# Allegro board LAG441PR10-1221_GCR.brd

Outline 316.12 x 80.43 mm; copper layers: TOP, GND1, IN1, GND2, IN2, VCC, GND3, IN3, GND4, BOTTOM. Coordinates in mm from the lower left corner of the outline.

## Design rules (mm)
net group CHG_CSI: nets CHG_CSIN CHG_CSIP
net group CHG_CSON: nets CHG_CSON N30249106
net group CHG_CSOP: nets CHG_CSOP N30248348
net group CLK_ITPXDP_: nets CLK_ITPXDP_N CLK_ITPXDP_P
net group DDR_B_DQS5: nets DDR_B_DQS5 DDR_B_DQS#5
net group DDR_B_DQS6: nets DDR_B_DQS6 DDR_B_DQS#6
net group DDR_B_DQS7: nets DDR_B_DQS7 DDR_B_DQS#7
net group DDRA-DQS0: nets DDR_A_DQS0 DDR_A_DQS#0
net group DDRA-DQS1: nets DDR_A_DQS1 DDR_A_DQS#1
net group DDRA-DQS2: nets DDR_A_DQS2 DDR_A_DQS#2
net group DDRA-DQS3: nets DDR_A_DQS3 DDR_A_DQS#3
net group DDRA-DQS4: nets DDR_A_DQS4 DDR_A_DQS#4
net group DDRA-DQS5: nets DDR_A_DQS5 DDR_A_DQS#5
net group DDRA-DQS6: nets DDR_A_DQS6 DDR_A_DQS#6
net group DDRA-DQS7: nets DDR_A_DQS7 DDR_A_DQS#7
net group DDRB-DQS0: nets DDR_B_DQS0 DDR_B_DQS#0
net group DDRB-DQS1: nets DDR_B_DQS1 DDR_B_DQS#1
net group DDRB-DQS2: nets DDR_B_DQS2 DDR_B_DQS#2
net group DDRB-DQS3: nets DDR_B_DQS3 DDR_B_DQS#3
net group DDRB_DQS4: nets DDR_B_DQS4 DDR_B_DQS#4
net group DIFFPAIR10: nets ISH_I2C0_SCL_EDP ISH_I2C0_SDA_EDP
net group DIFFPAIR11: nets DMIC_CLK DMIC_DATA12
net group DIFFPAIR12: nets PCH_DMIC_CLK0 PCH_DMIC_DATA0
net group DIFFPAIR15: nets CPU_DP2_CTRL_CLK CPU_DP2_CTRL_DATA
net group DIFFPAIR16: nets TBT_DP1_CLK TBT_DP1_DATA
net group DIFFPAIR17: nets CPU_DP1_CTRL_CLK CPU_DP1_CTRL_DATA
net group DIFFPAIR18: nets DMIC_CLK_UA1 DMIC_DATA_UA1
net group DP2: nets VCC_SENSE VSS_SENSE
net group DP4: nets PCH_CL_CLK1 PCH_CL_DATA1
net group DP5: nets EC_TP_I2C_CLK EC_TP_I2C_DAT
net group DP6: nets TS_I2C_SCL TS_I2C_SDA
net group DP7: nets TP_I2C_DAT TP_I2C_SCL
net group DP8: nets SML1_SMBCLK SML1_SMBDATA
net group DP9: nets I2C1_SCK_TP I2C1_SDA_TP
net group DP10: nets DDR_XDP_SMBCLK DDR_XDP_SMBDAT
net group DP11: nets UPD2_SMBCLK UPD2_SMBDAT
net group DP12: nets UPD1_SMBCLK UPD1_SMBDAT
net group DP13: nets USH_EXPANDER_SMBCLK USH_EXPANDER_SMBDAT
net group DP14: nets TBT_I2C_CLK TBT_I2C_DATA
net group DP15: nets USB20_N9_L USB20_P9_L
net group DP16: nets VCCSA_SENSE VSSSA_SENSE
net group DP17: nets CLK_PCIE_N0 CLK_PCIE_P0
net group HDMI_R_CLK: nets HDMI_R_CLKN HDMI_R_CLKP
net group HDMI_R_TX_0: nets HDMI_R_TX_N0 HDMI_R_TX_P0
net group HDMI_R_TX_1: nets HDMI_R_TX_N1 HDMI_R_TX_P1
net group HDMI_R_TX_2: nets HDMI_R_TX_N2 HDMI_R_TX_P2
net group PCH_RTCX1: nets PCH_RTCX1 PCH_RTCX1_R
net group PCH_RTCX2: nets PCH_RTCX2 PCH_RTCX2_R
net group SPK_OUT_L: nets SPK_OUT_L+ SPK_OUT_L-
net group SPK_OUT_R: nets SPK_OUT_R+ SPK_OUT_R-
net group USB3_PRX_DTX_3: nets USB3_PRX_DTX_N3 USB3_PRX_DTX_P3
net group USB3_PRX_L_DTX_3: nets USB3_PRX_L_DTX_N3 USB3_PRX_L_DTX_P3
net group USB3_PRX_RD_DTX_N3: nets USB3_PRX_RD_DTX_N3 USB3_PRX_RD_DTX_P3
net group USB3_PTX_C_DRX_N3: nets USB3_PTX_C_DRX_N3 USB3_PTX_C_DRX_P3
net group USB3_PTX_C_DRX_N4: nets USB3_PTX_C_DRX_N4 USB3_PTX_DRX_N4
net group USB3_PTX_C_DRX_P4: nets USB3_PTX_C_DRX_P4 USB3_PTX_DRX_P4
net group USB3_PTX_RD_DRX_N3: nets USB3_PTX_RD_DRX_N3 USB3_PTX_RD_DRX_P3
net group VCCGT_SENSE: nets VCCGT_SENSE VCCGT_SENSE_R
net group VSSGT_SENSE: nets VSSGT_SENSE VSSGT_SENSE_R
net group XTAL24_IN: nets XTAL24_IN XTAL24_IN_R
net group XTAL24_OUT: nets XTAL24_OUT XTAL24_OUT_R
net group AR: nets TBT_A_AUX_N TBT_A_AUX_N_C TBT_A_AUX_P TBT_A_AUX_P_C TBT_A_TRX_DTX_N1 TBT_A_TRX_DTX_N2 TBT_A_TRX_DTX_P1 TBT_A_TRX_DTX_P2 TBT_A_TTX_C_DRX_N1 TBT_A_TTX_C_DRX_N2 TBT_A_TTX_C_DRX_P1 TBT_A_TTX_C_DRX_P2 TBT_A_TTX_DRX_N1 TBT_A_TTX_DRX_N2 TBT_A_TTX_DRX_P1 TBT_A_TTX_DRX_P2 TBT_B_AUX_N TBT_B_AUX_N_C TBT_B_AUX_P TBT_B_AUX_P_C TBT_B_TRX_DTX_N1 TBT_B_TRX_DTX_N2 TBT_B_TRX_DTX_P1 TBT_B_TRX_DTX_P2 TBT_B_TTX_C_DRX_N1 TBT_B_TTX_C_DRX_N2 TBT_B_TTX_C_DRX_P1 TBT_B_TTX_C_DRX_P2 TBT_B_TTX_DRX_N1 TBT_B_TTX_DRX_N2 TBT_B_TTX_DRX_P1 TBT_B_TTX_DRX_P2
net group AR-CONN: nets TBT_A_I2C_B_N TBT_A_I2C_B_N_R TBT_A_I2C_B_P TBT_A_I2C_B_P_R TBT_A_USB2_T_N TBT_A_USB2_T_N_R TBT_A_USB2_T_P TBT_A_USB2_T_P_R TBT_B_I2C_B_N TBT_B_I2C_B_N_R TBT_B_I2C_B_P TBT_B_I2C_B_P_R TBT_B_USB2_T_N TBT_B_USB2_T_N_R TBT_B_USB2_T_P TBT_B_USB2_T_P_R
net group CNVI: nets CLK_CNV_PRX_DTX_N CLK_CNV_PRX_DTX_P CLK_CNV_PTX_DRX_N CLK_CNV_PTX_DRX_P CNV_PRX_DTX_N0 CNV_PRX_DTX_N1 CNV_PRX_DTX_P0 CNV_PRX_DTX_P1 CNV_PTX_DRX_N0 CNV_PTX_DRX_N1 CNV_PTX_DRX_P0 CNV_PTX_DRX_P1
net group CNVI_S: nets CNV_BRI_PRX_DTX CNV_BRI_PRX_R_DTX CNV_BRI_PTX_R_DRX CNV_RGI_PRX_DTX CNV_RGI_PRX_R_DTX CNV_RGI_PTX_DRX CNV_RGI_PTX_R_DRX
net group CRYSTAL: nets MEC_XTAL1 MEC_XTAL2 MEC_XTAL2_R XTAL_25_IN XTAL_25_IN_R XTAL_25_OUT XTAL_25_OUT_R
net group DDI1: nets CPU_DP1_AUXN CPU_DP1_AUXN_C CPU_DP1_AUXP CPU_DP1_AUXP_C CPU_DP1_N0 CPU_DP1_N0_C CPU_DP1_N1 CPU_DP1_N1_C CPU_DP1_N2 CPU_DP1_N2_C CPU_DP1_N3 CPU_DP1_N3_C CPU_DP1_P0 CPU_DP1_P0_C CPU_DP1_P1 CPU_DP1_P1_C CPU_DP1_P2 CPU_DP1_P2_C CPU_DP1_P3 CPU_DP1_P3_C
net group DDI2: nets CPU_DP2_AUXN CPU_DP2_AUXN_C CPU_DP2_AUXP CPU_DP2_AUXP_C CPU_DP2_N0 CPU_DP2_N0_C CPU_DP2_N1 CPU_DP2_N1_C CPU_DP2_N2 CPU_DP2_N2_C CPU_DP2_N3 CPU_DP2_N3_C CPU_DP2_P0 CPU_DP2_P0_C CPU_DP2_P1 CPU_DP2_P1_C CPU_DP2_P2 CPU_DP2_P2_C CPU_DP2_P3 CPU_DP2_P3_C
net group DDR-OTHER: nets DDR_A0_ZQ0 DDR_A0_ZQ1 DDR_A1_ZQ0 DDR_A1_ZQ1 DDR_B0_ZQ0 DDR_B0_ZQ1 DDR_B1_ZQ0 DDR_B1_ZQ1
net group DDR_A_CA1: nets DDR_A_CA1_0 DDR_A_CA1_1 DDR_A_CA1_2 DDR_A_CA1_3 DDR_A_CA1_4 DDR_A_CA1_5 DDR_A_CA1_6 DDR_A_CA1_7 DDR_A_CA1_8 DDR_A_CA1_9
net group DDR_A_CA2: nets DDR_A_CA2_0 DDR_A_CA2_1 DDR_A_CA2_2 DDR_A_CA2_3 DDR_A_CA2_4 DDR_A_CA2_5 DDR_A_CA2_6 DDR_A_CA2_7 DDR_A_CA2_8 DDR_A_CA2_9
net group DDR_A_CKE: nets DDR_A_CKE0 DDR_A_CKE1 DDR_A_CKE2 DDR_A_CKE3
net group DDR_B_CA1: nets DDR_B_CA1_0 DDR_B_CA1_1 DDR_B_CA1_2 DDR_B_CA1_3 DDR_B_CA1_4 DDR_B_CA1_5 DDR_B_CA1_6 DDR_B_CA1_7 DDR_B_CA1_8 DDR_B_CA1_9
net group DDR_B_CA2: nets DDR_B_CA2_0 DDR_B_CA2_1 DDR_B_CA2_2 DDR_B_CA2_3 DDR_B_CA2_4 DDR_B_CA2_5 DDR_B_CA2_6 DDR_B_CA2_7 DDR_B_CA2_8 DDR_B_CA2_9
net group DDR_B_CKE: nets DDR_B_CKE0 DDR_B_CKE1 DDR_B_CKE2 DDR_B_CKE3
net group DDRA-D0: nets DDR_A_D0 DDR_A_D1 DDR_A_D2 DDR_A_D3 DDR_A_D4 DDR_A_D5 DDR_A_D6 DDR_A_D7
net group DDRA-D1: nets DDR_A_D8 DDR_A_D9 DDR_A_D10 DDR_A_D11 DDR_A_D12 DDR_A_D13 DDR_A_D14 DDR_A_D15
net group DDRA-D2: nets DDR_A_D16 DDR_A_D17 DDR_A_D18 DDR_A_D19 DDR_A_D20 DDR_A_D21 DDR_A_D22 DDR_A_D23
net group DDRA-D3: nets DDR_A_D24 DDR_A_D25 DDR_A_D26 DDR_A_D27 DDR_A_D28 DDR_A_D29 DDR_A_D30 DDR_A_D31
net group DDRA-D4: nets DDR_A_D32 DDR_A_D33 DDR_A_D34 DDR_A_D35 DDR_A_D36 DDR_A_D37 DDR_A_D38 DDR_A_D39
net group DDRA-D5: nets DDR_A_D40 DDR_A_D41 DDR_A_D42 DDR_A_D43 DDR_A_D44 DDR_A_D45 DDR_A_D46 DDR_A_D47
net group DDRA-D6: nets DDR_A_D48 DDR_A_D49 DDR_A_D50 DDR_A_D51 DDR_A_D52 DDR_A_D53 DDR_A_D54 DDR_A_D55
net group DDRA-D7: nets DDR_A_D56 DDR_A_D57 DDR_A_D58 DDR_A_D59 DDR_A_D60 DDR_A_D61 DDR_A_D62 DDR_A_D63
net group DDRB-D0: nets DDR_B_D0 DDR_B_D1 DDR_B_D2 DDR_B_D3 DDR_B_D4 DDR_B_D5 DDR_B_D6 DDR_B_D7
net group DDRB-D1: nets DDR_B_D8 DDR_B_D9 DDR_B_D10 DDR_B_D11 DDR_B_D12 DDR_B_D13 DDR_B_D14 DDR_B_D15
net group DDRB-D2: nets DDR_B_D16 DDR_B_D17 DDR_B_D18 DDR_B_D19 DDR_B_D20 DDR_B_D21 DDR_B_D22 DDR_B_D23
net group DDRB-D3: nets DDR_B_D24 DDR_B_D25 DDR_B_D26 DDR_B_D27 DDR_B_D28 DDR_B_D29 DDR_B_D30 DDR_B_D31
net group DDRB-D4: nets DDR_B_D32 DDR_B_D33 DDR_B_D34 DDR_B_D35 DDR_B_D36 DDR_B_D37 DDR_B_D38 DDR_B_D39
net group DDRB-D5: nets DDR_B_D40 DDR_B_D41 DDR_B_D42 DDR_B_D43 DDR_B_D44 DDR_B_D45 DDR_B_D46 DDR_B_D47
net group DDRB-D6: nets DDR_B_D48 DDR_B_D49 DDR_B_D50 DDR_B_D51 DDR_B_D52 DDR_B_D53 DDR_B_D54 DDR_B_D55
net group DDRB-D7: nets DDR_B_D56 DDR_B_D57 DDR_B_D58 DDR_B_D59 DDR_B_D60 DDR_B_D61 DDR_B_D62 DDR_B_D63
net group EDP: nets EDP_AUXN EDP_AUXN_R EDP_AUXP EDP_AUXP_R EDP_TXN0 EDP_TXN0_R EDP_TXN1 EDP_TXN1_R EDP_TXP0 EDP_TXP0_R EDP_TXP1 EDP_TXP1_R
net group HDMI: nets TBT_DP0_N0 TBT_DP0_P0 TBT_DP1_N1 TBT_DP1_P1 TBT_DP2_N2 TBT_DP2_P2 TBT_DP3_N3 TBT_DP3_P3
net group HDMI-100H: nets HDMI_CLKN HDMI_CLKP HDMI_TX_N0 HDMI_TX_N1 HDMI_TX_N2 HDMI_TX_P0 HDMI_TX_P1 HDMI_TX_P2
net group PCIE: nets PCIE_PRX_C_DTX_N1 PCIE_PRX_C_DTX_N9 PCIE_PRX_C_DTX_N10 PCIE_PRX_C_DTX_N11 PCIE_PRX_C_DTX_N12 PCIE_PRX_C_DTX_N13 PCIE_PRX_C_DTX_N14 PCIE_PRX_C_DTX_N15 PCIE_PRX_C_DTX_N16 PCIE_PRX_C_DTX_P1 PCIE_PRX_C_DTX_P9 PCIE_PRX_C_DTX_P10 PCIE_PRX_C_DTX_P11 PCIE_PRX_C_DTX_P12 PCIE_PRX_C_DTX_P13 PCIE_PRX_C_DTX_P14 PCIE_PRX_C_DTX_P15 PCIE_PRX_C_DTX_P16 PCIE_PRX_DTX_N1 PCIE_PRX_DTX_N6 PCIE_PRX_DTX_N7 PCIE_PRX_DTX_N8 PCIE_PRX_DTX_N9 PCIE_PRX_DTX_N10 PCIE_PRX_DTX_N11 PCIE_PRX_DTX_N12 PCIE_PRX_DTX_N13 PCIE_PRX_DTX_N14 PCIE_PRX_DTX_N15 PCIE_PRX_DTX_N16 PCIE_PRX_DTX_P1 PCIE_PRX_DTX_P6 PCIE_PRX_DTX_P7 PCIE_PRX_DTX_P8 PCIE_PRX_DTX_P9 PCIE_PRX_DTX_P10 PCIE_PRX_DTX_P11 PCIE_PRX_DTX_P12 PCIE_PRX_DTX_P13 PCIE_PRX_DTX_P14 PCIE_PRX_DTX_P15 PCIE_PRX_DTX_P16 PCIE_PTX_C_DRX_N1 PCIE_PTX_C_DRX_N6 PCIE_PTX_C_DRX_N7 PCIE_PTX_C_DRX_N9 PCIE_PTX_C_DRX_N10 PCIE_PTX_C_DRX_N11 PCIE_PTX_C_DRX_N12 PCIE_PTX_C_DRX_N13 PCIE_PTX_C_DRX_N14 PCIE_PTX_C_DRX_N15 PCIE_PTX_C_DRX_N16 PCIE_PTX_C_DRX_P1 PCIE_PTX_C_DRX_P6 PCIE_PTX_C_DRX_P7 PCIE_PTX_C_DRX_P8 PCIE_PTX_C_DRX_P9 PCIE_PTX_C_DRX_P10 PCIE_PTX_C_DRX_P11 PCIE_PTX_C_DRX_P12 PCIE_PTX_C_DRX_P13 PCIE_PTX_C_DRX_P14 PCIE_PTX_C_DRX_P15 PCIE_PTX_C_DRX_P16 PCIE_PTX_DRX_N6 PCIE_PTX_DRX_N7 PCIE_PTX_DRX_N9 PCIE_PTX_DRX_N10 PCIE_PTX_DRX_N11 PCIE_PTX_DRX_N12 PCIE_PTX_DRX_N13 PCIE_PTX_DRX_N14 PCIE_PTX_DRX_N15 PCIE_PTX_DRX_N16 PCIE_PTX_DRX_P6 PCIE_PTX_DRX_P7 PCIE_PTX_DRX_P9 PCIE_PTX_DRX_P10 PCIE_PTX_DRX_P11 PCIE_PTX_DRX_P12 PCIE_PTX_DRX_P13 PCIE_PTX_DRX_P14 PCIE_PTX_DRX_P15 PCIE_PTX_DRX_P16 USB3_MRX_DTX_N4 USB3_MRX_DTX_P4 USB3_MTX_DRX_N4 USB3_MTX_DRX_P4 USB3_PRX_DTX_N4 USB3_PRX_DTX_P4
net group PCIE_15: nets PCIE_PTX_DRX_N1 PCIE_PTX_DRX_N8 PCIE_PTX_DRX_P1 PCIE_PTX_DRX_P8
net group PLATFORM-CLK: nets CLK_PCIE_N1 CLK_PCIE_N1_R CLK_PCIE_N2 CLK_PCIE_N2_R CLK_PCIE_N4 CLK_PCIE_N4_R CLK_PCIE_N5 CLK_PCIE_N5_R CLK_PCIE_P1 CLK_PCIE_P1_R CLK_PCIE_P2 CLK_PCIE_P2_R CLK_PCIE_P4 CLK_PCIE_P4_R CLK_PCIE_P5 CLK_PCIE_P5_R CLKREQ_PCIE#0 CLKREQ_PCIE#1 CLKREQ_PCIE#2 CLKREQ_PCIE#3 CLKREQ_PCIE#4 CLKREQ_PCIE#5 PCIE_PRX_R_DTX_N8 PCIE_PRX_R_DTX_P8 PCIE_PTX_C_DRX_N8 PCIE_PTX_R_DRX_N8 PCIE_PTX_R_DRX_P8
net group S-5: nets BC_DAT_ECE1117 CHG_DAT CPU_XDP_TDI CPU_XDP_TDO CPU_XDP_TMS DAT_SMB IMVP_SMBDAT IMVP_VR_SMBDAT ISH_I2C0_SDA ISH_I2C0_SDA_R ISH_I2C1_SDA JTAG_TDI JTAG_TDO JTAG_TMS MEM_SMBDATA MSDATA PBAT_CHARGER_SMBDAT PCH_JTAG_TDI PCH_JTAG_TDO PCH_JTAG_TMS PCH_JTAGX PCH_SPI_CS0# PCH_SPI_CS0#_R PCH_SPI_CS1# PCH_SPI_CS1#_R PCH_SPI_CS2# PCH_SPI_CS2#_TPM PCH_SPI_IO2 PCH_SPI_IO2_R PCH_SPI_IO3 PCH_SPI_IO3_R PCH_SPI_SI PCH_SPI_SI_R PCH_SPI_SI_TPM PCH_SPI_SO PCH_SPI_SO_R PCH_SPI_SO_TPM PS_SMBDAT SD_CMD SD_CMD_R SD_D0 SD_D0_R SD_D1 SD_D1_R SD_D2 SD_D2_R SD_D3 SD_D3_R SML0_SMBDATA SP7_SDWP SPI_CLK_VROM0 SPI_IO2_VROM0 SPI_IO3_VROM0 SPI_SI_VROM0 SPI_SO_VROM0 SYS_PWROK TPM_PIRQ# TS_I2C_SDA_R UIM_DATA UPD1_SMBINT# UPD2_SMBINT# XDP_ITP_PMODE XDP_TCK0 XDP_TDI XDP_TDO XDP_TMS
net group S-9: nets BEEP CBN CBP CFG_RCOMP CHG_COMP CLK_TP_SIO_I2C_DAT CLKREQ_CNV CNV_RF_RESET CNV_RF_RESET# CNV_RF_RESET#_R CNVI_EN# CPU_POPIRCOMP CPU_XDP_TRST# CPVEE DMIC_CLK0 DMIC_DATA0 DPSNK1_DDC_CLK EDP_RCOMP EDRAM_OPIO_RCOMP EMMC_RCOMP EOPIO_RCOMP ESPI_ALERT# ESPI_CS# ESPI_IO0 ESPI_IO0_R ESPI_IO1 ESPI_IO1_R ESPI_IO2 ESPI_IO2_R ESPI_IO3 ESPI_IO3_R ESPI_RESET# FPR_RESET# H_CATERR# H_CPU_SVIDALRT# H_CPUPWRGD H_PROCHOT# H_PROCHOT#_R H_THERMTRIP# HDA_RST# HDA_RST#_R HDA_SDIN0 HDA_SDIN0_R HDA_SDOUT HDA_SDOUT_R HDA_SYNC HDA_SYNC_R HPOL_CONN HPOR_CONN HPOUT-L HPOUT-L_L HPOUT-R HPOUT-R_L HRESET_PD1 HRESET_PD2 JTAG_RST# LINE2-L LINE2-R MIC2-VREFO-L MIC2-VREFO-R MONO_IN PCH_CL_RST1# PCH_JTAG_TRST# PCH_PLTRST# PCH_PLTRST#_5105 PCH_PLTRST#_AND PCH_POPIRCOMP PCH_RSMRST# PCH_RSMRST#_AND PCH_RTCRST# PCH_TBT_PERST# PCIE_RCOMPN PCIE_RCOMPP PECI_EC PECI_EC_R REM_DIODE1_N REM_DIODE1_P REM_DIODE2_N REM_DIODE2_P REM_DIODE3_N REM_DIODE3_P RESET_IN# RESET_OUT RING2 RTCRST_ON RTCRST_ON_POWER RTCRST_ON_R SD_RCOMP SM_RCOMP0 SM_RCOMP1 SM_RCOMP2 SPKR SRTCRST# SYS_RESET# TBT_A_MRESET TBT_A_RESET_N TBT_B_RESET_N TBT_RESET_N_EC TBT_RESET_N_R TS_RST# TS_RST#_R UIM_RESET VCCST_PWRGD VCCST_PWRGD_CPU VIDSCLK_R VIDSOUT_R VR_SVID_ALERT# VR_SVID_CLK VR_SVID_DATA WWAN_BB_RST# WWAN_BB_RST#_R WWAN_GPIO_PERST# WWAN_GPIO_PERST#_R WWAN_PERST# WWAN_PERST#_R XDP_BPM#0 XDP_BPM#1 XDP_BPM#2_R XDP_BPM#3_R XDP_TRST#
net group S-12: nets BC_CLK_ECE1117 CHG_CLK CLK_SMB DAT_TP_SIO_I2C_CLK ESPI_CLK ESPI_CLK_5105 HDA_BIT_CLK HDA_BIT_CLK_R IMVP_SMBCLK IMVP_VR_SMBCLK ISH_I2C0_SCL ISH_I2C0_SCL_R ISH_I2C1_SCL MEM_SMBCLK MSCLK PBAT_CHARGER_SMBCLK PCH_SPI_CLK PCH_SPI_CLK_R PCH_SPI_CLK_TPM PS_SMBCLK SD_CLK SD_CLK_R SML0_SMBCLK TBT_A_CC1 TBT_A_CC2 TBT_B_CC1 TBT_B_CC2 TS_I2C_SCL_R UIM_CLK
net group SD-100H: nets SD_LN0_M SD_LN0_P SD_LN1_M SD_LN1_P
net group USB3_PTX_DRX_3: nets USB3_PTX_DRX_P3
net group USB3_PTX_L_DRX_3: nets USB3_PTX_L_DRX_N3
net group USB20: nets CHR_USB20_N3 CHR_USB20_N3_R CHR_USB20_N4 CHR_USB20_N4_R CHR_USB20_P3 CHR_USB20_P3_R CHR_USB20_P4 CHR_USB20_P4_R FP_USB+ FP_USB- USB20_N1 USB20_N2 USB20_N3 USB20_N4 USB20_N6 USB20_N6_R USB20_N7 USB20_N7_R USB20_N8 USB20_N8_R USB20_N9 USB20_N9_R USB20_N10 USB20_N10_R USB20_P1 USB20_P2 USB20_P3 USB20_P4 USB20_P6 USB20_P6_R USB20_P7 USB20_P7_R USB20_P8 USB20_P8_R USB20_P9 USB20_P9_R USB20_P10 USB20_P10_R
net group USB30: nets USB3_MRX_L_DTX_N4 USB3_MRX_L_DTX_P4 USB3_MTX_L_DRX_N4 USB3_MTX_L_DRX_P4 USB3_PRX_C_RD_DTX_N3 USB3_PRX_C_RD_DTX_P3 USB3_PRX_DTX_N2 USB3_PRX_DTX_P2 USB3_PRX_L_DTX_N2 USB3_PRX_L_DTX_P2 USB3_PTX_C_DRX_N2 USB3_PTX_C_DRX_P2 USB3_PTX_C_RD_DRX_N3 USB3_PTX_C_RD_DRX_P3 USB3_PTX_DRX_N2 USB3_PTX_DRX_N3 USB3_PTX_DRX_P2 USB3_PTX_L_DRX_N2 USB3_PTX_L_DRX_P2 USB3_PTX_L_DRX_P3
net group W10: nets TBT_RSENSE VBUSSENSE VCC_SENSE_R VSS_SENSE_R
net group XDP_4/3/3/3/4: nets CPU_XDP_TCK JTAG_CLK PCH_JTAG_TCK XDP_TCK1
nets with their own width: min track width 0.254; nets BAT1_LED#_R BAT2_LED#_R CAPS_LED F4_LED
nets with their own width: min track width 0.381; nets +3V_PCH_DSW_R
nets with their own width: min track width 0.508; nets +1.0V_VCCSTG_R +3V_FPR +3V_PCH AGND CHG_ADP GND KB_LED_PWM# VDD
nets with their own width: min track width 0.762; nets CHG_DCIN
nets with their own width: min track width 1.016; nets B+ RING2_CONN SLEEVE SLEEVE_CONN

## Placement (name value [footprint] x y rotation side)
C14  0.1U_0201_10V6K  [C_0201]  133.36 16.39 270 bottom
C15  100P_0201_50V8J  [C_0201]  303.32 64.8 0 bottom
C18  0.1U_0201_10V6K  [C_0201]  303.32 64.22 0 bottom
C21  0.1U_0201_10V6K  [C_0201]  200.89 32.11 90 bottom
C22  10U_0402_10V6M  [C_0402]  201.7 32.02 0 bottom
C26  0.1U_0201_10V6K  [C_0201]  188.89 19.28 90 bottom
C27  470P_0201_25V7K  [C_0201]  185.33 17.51 90 bottom
C28  1U_0201_6.3V6M  [C_0201]  254.1 42.08 90 top
C29  0.1U_0201_10V6K  [C_0201]  257.28 36.11 90 top
C30  470P_0201_25V7K  [C_0201]  48.09 74.81 90 top
C31  0.1U_0201_10V6K  [C_0201]  185.77 12.76 270 bottom
C32  0.1U_0201_10V6K  [C_0201]  47.24 69.45 90 top
C37  470P_0201_25V7K  [C_0201]  255.5 36.7 270 top
C38  470P_0201_25V7K  [C_0201]  254.86 36.7 270 top
C39  1U_0201_6.3V6M  [C_0201]  256.13 42.08 90 top
C41  0.1U_0201_10V6K  [C_0201]  253 36.11 90 top
C48  0.1U_0201_10V6K  [C_0201]  201.84 32.44 270 top
C49  1U_0201_6.3V6M  [C_0201]  195.59 33.07 180 top
C50  470P_0201_25V7K  [C_0201]  200.14 32.52 0 top
C51  470P_0201_25V7K  [C_0201]  200.14 31.57 0 top
C52  0.1U_0201_10V6K  [C_0201]  202.41 30.5 0 top
C53  1U_0201_6.3V6M  [C_0201]  195.59 31.92 180 top
C56  0.1U_0201_10V6K  [C_0201]  221.84 62.1 270 top
C57  0.1U_0201_10V6K  [C_0201]  224 56.64 270 top
C59  1000P_0201_50V7K  [C_0201]  224.89 61.51 90 top
C60  470P_0201_25V7K  [C_0201]  222.48 50.78 90 top
C61  0.1U_0201_10V6K  [C_0201]  227.05 50.27 90 top
C62  0.1U_0201_10V6K  [C_0201]  221.93 47.64 0 top
C70  0.1U_0201_10V6K  [C_0201]  120.5 29.1 0 top
C71  470P_0201_25V7K  [C_0201]  123.61 31.51 0 top
C72  1U_0201_6.3V6M  [C_0201]  121.7 28.28 90 top
C73  470P_0201_25V7K  [C_0201]  124.81 31.51 0 top
C74  0.1U_0201_10V6K  [C_0201]  128.31 30.41 90 top
C75  1U_0201_6.3V6M  [C_0201]  126.02 28.66 90 top
C78  0.1U_0201_10V6K  [C_0201]  48 76.38 0 top
C85  1U_0201_6.3V6M  [C_0201]  228.15 42.94 0 top
C86  1U_0201_6.3V6M  [C_0201]  227.68 50.27 90 top
C88  0.47U_0201_6.3V6K  [C_0201]  99.17 21.7 180 top
C92  2.2U_0201_6.3V6M  [C_0201]  148.67 20.22 270 bottom
C93  0.1U_0201_10V6K  [C_0201]  300.93 58.98 90 bottom
C94  0.1U_0201_10V6K  [C_0201]  33.63 51.96 270 top
C95  0.1U_0201_10V6K  [C_0201]  30.9 51.96 270 top
C96  0.33U_0201_6.3V6M  [C_0201]  136.17 17.49 90 bottom
C97  0.33U_0201_6.3V6M  [C_0201]  135.61 17.49 90 bottom
CA1  0.1U_0201_10V6K  [C_0201]  292.45 25.1 180 top
CA4  0.22U_0201_10V6K  [C_0201]  292.42 26.31 0 top
CA5  10U_0402_10V6M  [C_0402]  288.77 28.83 90 top
CA6  100P_0201_50V8J  [C_0201]  292.45 25.74 0 top
CA7  10U_0402_6.3V6M  [C_0402]  289.53 23.77 0 top
CA8  330P_0201_50V7K  [C_0201]  288.9 19.7 270 top
CA9  330P_0201_50V7K  [C_0201]  288.9 20.34 0 top
CA10  2.2U_0603_6.3V6K  [C_0603]  290.68 19.2 0 top
CA11  10U_0402_6.3V6M  [C_0402]  278.04 25.37 270 top
CA12  0.1U_0201_10V6K  [C_0201]  278.8 25.52 270 top
CA13  2.2U_0201_6.3V6M  [C_0201]  288.64 27.36 270 top
CA14  0.1U_0201_10V6K  [C_0201]  287.06 29 90 top
CA15  10U_0402_6.3V6M  [C_0402]  290.5 27.77 180 top
CA16  10U_0402_6.3V6M  [C_0402]  287.82 28.83 90 top
CA18  10U_0402_6.3V6M  [C_0402]  286.16 19.04 270 top
CA19  10U_0402_6.3V6M  [C_0402]  283.16 18.5 270 top
CA20  10U_0402_6.3V6M  [C_0402]  285.23 33.66 180 bottom
CA21  0.1U_0201_10V6K  [C_0201]  284.61 32.56 225 bottom
CA22  10U_0402_6.3V6M  [C_0402]  285.34 30.18 45 bottom
CA23  0.1U_0201_10V6K  [C_0201]  284.43 31.06 135 bottom
CA24  0.1U_0201_10V6K  [C_0201]  284.71 19.2 0 top
CA25  10U_0402_6.3V6M  [C_0402]  284.38 18.43 0 top
CA26  10U_0402_6.3V6M  [C_0402]  281.66 18.45 270 top
CA27  0.1U_0201_10V6K  [C_0201]  282.42 18.6 270 top
CA28  22P_0201_25V8  [C_0201]  280.75 19.7 180 top
CA29  10U_0402_6.3V6M  [C_0402]  280.39 29.09 90 top
CA30  0.1U_0201_10V6K  [C_0201]  281.15 29 90 top
CA31  0.1U_0201_10V6K  [C_0201]  278.21 26.12 180 top
CA32  1U_0201_6.3V6M  [C_0201]  277.62 26.75 0 top
CA34  33P_0201_50V8J  [C_0201]  276.72 23.58 180 top
CA35  10P_0201_50V8J  [C_0201]  276.72 22.94 180 top
CA36  0.1U_0201_10V6K  [C_0201]  279.59 29.03 90 top
CA42  10U_0603_6.3V6M  [C_0603]  289.66 26.05 0 top
CA43  10U_0603_6.3V6M  [C_0603]  289.66 24.85 0 top
CA44  100P_0201_50V8J  [C_0201]  292.42 20.34 0 top
CA45  100P_0201_50V8J  [C_0201]  292.45 24.53 180 top
CA46  680P_0201_50V7K  [C_0201]  299.06 15.64 180 top
CA47  680P_0201_50V7K  [C_0201]  294.93 25.8 90 top
CA48  100P_0201_50V8J  [C_0201]  291.95 21.61 270 top
CA49  100P_0201_50V8J  [C_0201]  291.95 22.88 270 top
CA84  1000P_0201_50V7K  [C_0201]  295.21 13.88 180 top
CA85  1000P_0201_50V7K  [C_0201]  296.65 13.88 0 top
CA86  1000P_0201_50V7K  [C_0201]  293.1 13.88 0 top
CA87  1000P_0201_50V7K  [C_0201]  291.65 13.88 180 top
CA141  0.1U_0201_10V6K  [C_0201]  281.14 12.07 90 top
CA144  470P_0201_25V7K  [C_0201]  266.55 36.7 270 top
CA145  1000P_0201_50V7K  [C_0201]  265.98 36.7 270 top
CA146  1U_0201_6.3V6M  [C_0201]  265.21 42.08 90 top
CA147  0.1U_0201_10V6K  [C_0201]  266.04 35.45 270 top
CA148  0.1U_0201_10V6K  [C_0201]  268.32 36.11 90 top
CA149  1U_0201_6.3V6M  [C_0201]  267.25 42.08 90 top
CA150  680P_0201_50V7K  [C_0201]  305.79 24.78 90 top
CA151  680P_0201_50V7K  [C_0201]  303.63 24.78 90 top
CA152  2.2U_0603_6.3V6K  [C_0603]  287.41 18.01 90 top
CA153  0.1U_0201_10V6K  [C_0201]  281.52 16.49 270 top
CA154  2P_0201_25V8B  [C_0201]  279.54 19.13 180 top
CA155  470P_0201_25V7K  [C_0201]  283.44 15.08 0 top
CB15  1U_0201_6.3V6M  [C_0201]  310.23 5.1 180 top
CB16  1U_0201_6.3V6M  [C_0201]  308.42 4.34 0 top
CB17  22P_0201_25V8  [C_0201]  310.62 1.69 90 top
CB18  0.1U_0201_10V6K  [C_0201]  312.3 4.59 0 top
CB19  0.1U_0201_10V6K  [C_0201]  268.52 14.92 270 top
CB20  0.1U_0201_10V6K  [C_0201]  269.79 14.92 270 top
CB21  0.1U_0201_10V6K  [C_0201]  267.25 14.92 270 top
CB22  0.1U_0201_10V6K  [C_0201]  271.06 14.92 270 top
CC2  12P_0201_50V8J  [C_0201]  102.31 30.54 0 top
CC4  0.1U_0201_10V6K  [C_0201]  104.11 12.05 90 top
CC6  15P_0201_50V8J  [C_0201]  108.91 59.61 0 bottom
CC7  15P_0201_50V8J  [C_0201]  107.16 59.61 180 bottom
CC8  10P_0201_50V8J  [C_0201]  98.78 25.93 0 bottom
CC9  1U_0201_6.3V6M  [C_0201]  98.91 30.63 270 bottom
CC10  10P_0201_50V8J  [C_0201]  98.14 25.93 180 bottom
CC11  1U_0201_6.3V6M  [C_0201]  96.91 28.09 180 bottom
CC12  0.01U_0201_10V6K  [C_0201]  99.8 27.83 270 bottom
CC13  22P_0201_25V8  [C_0201]  96.87 30.63 270 bottom
CC15  2P_0201_25V8B  [C_0201]  96.24 29.36 270 bottom
CC17  2P_0201_25V8B  [C_0201]  94.97 29.36 180 bottom
CC31  10U_0402_6.3V6M  [C_0402]  94.25 29.28 0 top
CC32  22U_0603_6.3V6M  [C_0603]  83.48 30.37 180 bottom
CC33  10U_0402_6.3V6M  [C_0402]  90.99 30.64 270 bottom
CC34  10U_0402_6.3V6M  [C_0402]  84.48 30.6 0 bottom
CC35  10U_0402_6.3V6M  [C_0402]  81.08 30.5 180 bottom
CC36  10U_0402_6.3V6M  [C_0402]  86.26 30.6 0 bottom
CC37  10U_0402_6.3V6M  [C_0402]  88.95 30.6 180 bottom
CC38  10U_0402_6.3V6M  [C_0402]  89.95 30.64 270 bottom
CC39  10U_0402_6.3V6M  [C_0402]  95.39 45.81 90 top
CC40  10U_0402_6.3V6M  [C_0402]  82.36 41.52 180 top
CC41  10U_0402_6.3V6M  [C_0402]  95.97 42.18 0 top
CC42  10U_0402_6.3V6M  [C_0402]  83.25 41.5 0 top
CC45  10U_0402_6.3V6M  [C_0402]  96.9 26.21 90 top
CC46  10U_0402_6.3V6M  [C_0402]  73.82 25.98 90 top
CC47  1U_0201_6.3V6M  [C_0201]  71.56 29.36 0 top
CC48  1U_0201_6.3V6M  [C_0201]  96.11 26.21 90 top
CC49  1U_0201_6.3V6M  [C_0201]  81.76 27.04 270 top
CC50  1U_0201_6.3V6M  [C_0201]  74.59 25.82 90 top
CC51  10U_0402_6.3V6M  [C_0402]  95.97 43.07 0 top
CC52  10U_0402_6.3V6M  [C_0402]  96.3 45.81 90 top
CC53  1U_0201_6.3V6M  [C_0201]  97.13 45.64 0 top
CC54  1U_0201_6.3V6M  [C_0201]  92.99 40.99 180 top
CC55  1U_0201_6.3V6M  [C_0201]  83.25 39.83 0 top
CC56  1U_0201_6.3V6M  [C_0201]  82.37 39.83 180 top
CC65  1U_0201_6.3V6M  [C_0201]  99.1 41.17 90 top
CC66  1U_0201_6.3V6M  [C_0201]  100.43 44.98 0 top
CC67  1U_0201_6.3V6M  [C_0201]  97.7 43.66 90 top
CC68  1U_0201_6.3V6M  [C_0201]  97.13 43.83 90 top
CC69  1U_0201_6.3V6M  [C_0201]  109.31 43.02 90 top
CC70  22U_0603_6.3V6M  [C_0603]  100.07 47.67 180 top
CC72  0.1U_0201_10V6K  [C_0201]  98.27 42.4 90 top
CC73  1U_0201_6.3V6M  [C_0201]  97.7 42.4 90 top
CC76  1U_0201_6.3V6M  [C_0201]  97.7 41.13 90 top
CC80  1U_0201_6.3V6M  [C_0201]  99.72 57.48 0 bottom
CC83  1U_0201_6.3V6M  [C_0201]  113.16 53.43 0 bottom
CC85  0.1U_0201_10V6K  [C_0201]  56.72 67.84 180 top
CC86  0.1U_0201_10V6K  [C_0201]  56.72 67.27 180 top
CC87  0.1U_0201_10V6K  [C_0201]  54.43 67.76 0 top
CC88  0.1U_0201_10V6K  [C_0201]  60.83 67.58 0 top
CC89  0.1U_0201_10V6K  [C_0201]  58.48 67.84 0 top
CC92  0.1U_0201_6.3V6K  [C_0201]  56.35 30.96 270 bottom
CC98  1U_0201_6.3V6M  [C_0201]  111.68 45.27 0 bottom
CC100  22U_0603_6.3V6M  [C_0603]  113 54.32 0 bottom
CC101  1U_0201_6.3V6M  [C_0201]  98.27 41.13 90 top
CC102  22U_0603_6.3V6M  [C_0603]  99.67 58.64 180 bottom
CC199  100P_0201_50V8J  [C_0201]  85.57 57.83 90 bottom
CC200  100P_0201_50V8J  [C_0201]  93.59 59.03 180 bottom
CC201  1U_0201_6.3V6M  [C_0201]  92.43 59.05 90 bottom
CC202  1U_0201_6.3V6M  [C_0201]  97.14 57.37 90 bottom
CC203  1U_0201_6.3V6M  [C_0201]  95.39 40.4 180 top
CC232  10U_0402_6.3V6M  [C_0402]  96.04 41.29 0 top
CC233  0.1U_0201_6.3V6K  [C_0201]  95.39 39.83 180 top
CC234  10U_0402_6.3V6M  [C_0402]  83.25 40.58 0 top
CC235  10U_0402_6.3V6M  [C_0402]  96.3 44.87 270 top
CC236  10U_0402_6.3V6M  [C_0402]  82.35 40.6 180 top
CC237  10U_0402_6.3V6M  [C_0402]  94.26 41.23 0 top
CC238  0.1U_0201_10V6K  [C_0201]  118.31 43.02 90 bottom
CC239  0.1U_0201_10V6K  [C_0201]  99.22 20.21 180 bottom
CC240  1U_0201_6.3V6M  [C_0201]  97.92 48.06 270 top
CC241  22U_0603_6.3V6M  [C_0603]  96.46 49.02 270 top
CC242  0.1U_0201_6.3V6K  [C_0201]  97.34 48.06 270 top
CC243  0.1U_0201_10V6K  [C_0201]  111.73 38.03 270 bottom
CC244  1U_0201_6.3V6M  [C_0201]  112.37 38.03 270 bottom
CC245  4.7U_0402_6.3V6M  [C_0402]  109.83 40.28 0 top
CC246  27P_0201_25V8  [C_0201]  112.85 40.65 0 bottom
CC247  27P_0201_25V8  [C_0201]  112.85 41.2 0 bottom
CC248  0.33U_0201_6.3V6M  [C_0201]  100.18 30.02 90 bottom
CC249  0.33U_0201_6.3V6M  [C_0201]  99.41 40.51 270 top
CC250  0.33U_0201_6.3V6M  [C_0201]  100.18 28.81 90 bottom
CC251  0.33U_0201_6.3V6M  [C_0201]  102.2 29.32 90 top
CC252  0.33U_0201_6.3V6M  [C_0201]  119.01 27.64 180 bottom
CC253  0.1U_0201_10V6K  [C_0201]  119.73 51.38 270 bottom
CC254  0.1U_0201_10V6K  [C_0201]  116.14 26.61 90 bottom
CC255  0.1U_0201_10V6K  [C_0201]  126.6 44.23 270 bottom
CC257  1U_0201_6.3V6M  [C_0201]  122.07 34.59 0 bottom
CC258  0.33U_0201_6.3V6M  [C_0201]  106.08 31.55 270 top
CC259  0.33U_0201_6.3V6M  [C_0201]  105.6 49.29 0 top
CC260  2.2P_0402_50V8C  [C_0402]  109.97 52.96 0 top
CC261  1U_0201_6.3V6M  [C_0201]  113.16 52.86 0 bottom
CC262  22U_0603_6.3V6M  [C_0603]  111.9 52.96 270 top
CC263  1U_0201_6.3V6M  [C_0201]  102.12 58.31 0 bottom
CC265  22U_0603_6.3V6M  [C_0603]  99.67 59.85 180 bottom
CD1  10U_0402_6.3V6M  [C_0402]  88.57 13.99 0 top
CD2  10U_0402_6.3V6M  [C_0402]  72.74 25.98 90 top
CD3  10U_0402_6.3V6M  [C_0402]  63.68 29.23 180 top
CD4  0.1U_0201_10V6K  [C_0201]  86.12 29.03 0 top
CD5  1U_0201_6.3V6M  [C_0201]  87.93 29.03 0 top
CD6  0.1U_0201_10V6K  [C_0201]  89.7 29.03 0 top
CD7  1U_0201_6.3V6M  [C_0201]  81.88 20.77 90 top
CD8  1U_0201_6.3V6M  [C_0201]  81.88 23.69 270 top
CD9  1U_0201_6.3V6M  [C_0201]  66.99 29.1 0 top
CD10  1U_0201_6.3V6M  [C_0201]  82.41 14.08 90 top
CD11  1U_0201_6.3V6M  [C_0201]  72.62 24.62 90 top
CD12  10U_0402_6.3V6M  [C_0402]  71.91 29.29 0 bottom
CD13  1U_0201_6.3V6M  [C_0201]  92.93 29.03 0 top
CD14  1U_0201_6.3V6M  [C_0201]  72.62 23.35 90 top
CD15  1U_0201_6.3V6M  [C_0201]  84.7 29.03 0 top
CD16  0.1U_0201_10V6K  [C_0201]  58.18 23.01 180 top
CD17  10U_0402_6.3V6M  [C_0402]  58.09 23.89 180 top
CD18  1U_0201_6.3V6M  [C_0201]  61.95 29.1 180 top
CD19  0.047U_0201_10V6K  [C_0201]  58.18 19.58 180 top
CD20  0.022U_0201_6.3V6K  [C_0201]  69.63 29.59 270 bottom
CD21  0.047U_0201_10V6K  [C_0201]  66.84 29 90 bottom
CD22  0.047U_0201_10V6K  [C_0201]  63.95 15.43 270 top
CD23  1U_0201_6.3V6M  [C_0201]  65.69 14.27 180 top
CD24  1U_0201_6.3V6M  [C_0201]  67.16 14.24 180 top
CD25  1U_0201_6.3V6M  [C_0201]  85.5 14 0 top
CD26  0.1U_0201_10V6K  [C_0201]  58.14 16.78 180 top
CD27  0.1U_0201_10V6K  [C_0201]  68.43 14.24 180 top
CD28  0.1U_0201_10V6K  [C_0201]  58.14 16.15 180 top
CD29  1U_0201_6.3V6M  [C_0201]  91.4 29.03 0 top
CD30  1U_0201_6.3V6M  [C_0201]  58.14 15.51 180 top
CD31  10U_0402_6.3V6M  [C_0402]  63.67 14.1 180 top
CD32  10U_0402_6.3V6M  [C_0402]  70.79 29.36 180 top
CD33  1U_0201_6.3V6M  [C_0201]  58.18 25.29 180 top
CD34  1U_0201_6.3V6M  [C_0201]  96.05 20.12 0 top
CD35  1U_0201_6.3V6M  [C_0201]  96.05 20.99 0 top
CD36  1U_0201_6.3V6M  [C_0201]  72.62 22.08 90 top
CD37  1U_0201_6.3V6M  [C_0201]  69.1 29.1 180 top
CD38  1U_0201_6.3V6M  [C_0201]  61.42 14.27 180 top
CD39  1U_0201_6.3V6M  [C_0201]  58.18 24.66 180 top
CD40  10U_0402_6.3V6M  [C_0402]  72.74 20.39 90 top
CD41  10U_0402_6.3V6M  [C_0402]  72.74 18.61 90 top
CD46  0.022U_0201_6.3V6K  [C_0201]  57.63 29.1 180 top
CD47  0.047U_0201_10V6K  [C_0201]  90.07 15.44 270 bottom
CD48  10U_0402_6.3V6M  [C_0402]  96.18 20.02 0 bottom
CD49  10U_0402_6.3V6M  [C_0402]  81.63 20.67 270 bottom
CD50  10U_0402_6.3V6M  [C_0402]  58.09 20.34 180 top
CD51  1U_0201_6.3V6M  [C_0201]  87.07 13.92 0 top
CD52  1U_0201_6.3V6M  [C_0201]  91.04 14.02 0 top
CD53  1U_0201_6.3V6M  [C_0201]  81.76 27.07 270 bottom
CD54  1U_0201_6.3V6M  [C_0201]  58.18 21.23 180 top
CD55  1U_0201_6.3V6M  [C_0201]  81.88 19.2 90 top
CD56  1U_0201_6.3V6M  [C_0201]  71.16 29 90 bottom
CD57  0.1U_0201_10V6K  [C_0201]  58.14 14.24 180 top
CD58  1U_0201_6.3V6M  [C_0201]  69.06 14.24 0 top
CD59  10U_0402_6.3V6M  [C_0402]  60.65 29.36 180 top
CD60  1U_0201_6.3V6M  [C_0201]  66.27 29 90 bottom
CD61  1U_0201_6.3V6M  [C_0201]  65.7 29 90 bottom
CD62  10U_0402_6.3V6M  [C_0402]  58.09 22.24 180 top
CD63  1U_0201_6.3V6M  [C_0201]  58.14 14.88 180 top
CD64  10U_0402_6.3V6M  [C_0402]  84.48 29.36 0 bottom
CD65  1U_0201_6.3V6M  [C_0201]  63.82 29.1 0 bottom
CD66  1U_0201_6.3V6M  [C_0201]  81.13 14.12 90 top
CD67  0.022U_0201_6.3V6K  [C_0201]  68.79 30.75 270 bottom
CD68  1U_0201_6.3V6M  [C_0201]  92.65 29.03 0 bottom
CD70  0.047U_0201_10V6K  [C_0201]  89.15 29.03 0 bottom
CD71  0.047U_0201_10V6K  [C_0201]  65.04 29.1 180 top
CD72  0.047U_0201_10V6K  [C_0201]  88.15 15.43 270 top
CD73  10U_0402_6.3V6M  [C_0402]  87.53 29.36 0 bottom
CD74  0.1U_0201_10V6K  [C_0201]  62.55 29.1 0 bottom
CD75  1U_0201_6.3V6M  [C_0201]  91.48 29.03 0 bottom
CD76  1U_0201_6.3V6M  [C_0201]  90.32 29.03 0 bottom
CD77  1U_0201_6.3V6M  [C_0201]  61.28 29.1 0 bottom
CD78  1U_0201_6.3V6M  [C_0201]  81.76 14.12 90 top
CD79  1U_0201_6.3V6M  [C_0201]  60.04 14.24 180 top
CD80  10U_0402_6.3V6M  [C_0402]  56.23 17.42 270 bottom
CD81  10U_0402_6.3V6M  [C_0402]  80.24 13.99 90 top
CD82  1U_0201_6.3V6M  [C_0201]  92.43 13.99 0 top
CD83  1U_0201_6.3V6M  [C_0201]  58.27 20.94 90 bottom
CD84  1U_0201_6.3V6M  [C_0201]  58.27 19.16 90 bottom
CD85  1U_0201_6.3V6M  [C_0201]  86.17 29.23 0 bottom
CD100  1U_0201_6.3V6M  [C_0201]  70.97 14.53 270 top
CD101  1U_0201_6.3V6M  [C_0201]  81.76 18.85 270 bottom
CD102  1U_0201_6.3V6M  [C_0201]  81.76 22.03 270 bottom
CD103  1U_0201_6.3V6M  [C_0201]  70.33 14.53 270 top
CD104  10U_0402_6.3V6M  [C_0402]  76.55 15.45 270 top
CD105  1U_0201_6.3V6M  [C_0201]  60.39 14.84 90 bottom
CD106  1U_0201_6.3V6M  [C_0201]  93.83 14.53 270 top
CD107  1U_0201_6.3V6M  [C_0201]  94.03 14.84 90 bottom
CD108  1U_0201_6.3V6M  [C_0201]  94.46 14.53 270 top
CD109  10U_0402_6.3V6M  [C_0402]  77.95 15.45 270 top
CD111  0.047U_0201_10V6K  [C_0201]  66.25 15.43 270 bottom
CD112  10U_0402_6.3V6M  [C_0402]  78.9 15.46 270 top
CD113  10U_0402_6.3V6M  [C_0402]  75.48 15.46 270 top
CE1  0.1U_0201_10V6K  [C_0201]  260.43 63.39 180 top
CE2  0.1U_0201_10V6K  [C_0201]  269.21 48.79 0 top
CE3  1U_0201_6.3V6M  [C_0201]  267.22 63.39 180 top
CE4  0.1U_0201_10V6K  [C_0201]  260.43 53.49 180 top
CE5  10U_0402_6.3V6M  [C_0402]  276.88 58.12 0 top
CE6  0.1U_0201_10V6K  [C_0201]  269.21 49.42 0 top
CE7  22U_0603_6.3V6M  [C_0603]  257.97 56.98 0 top
CE8  0.1U_0201_10V6K  [C_0201]  260.2 57.27 270 top
CE9  0.1U_0201_10V6K  [C_0201]  260.2 55.9 270 top
CE10  0.1U_0201_10V6K  [C_0201]  274.38 57.23 0 top
CE11  12P_0201_50V8J  [C_0201]  277.27 59.44 0 top
CE12  68P_0201_50V8J  [C_0201]  277.27 58.87 0 top
CE14  0.1U_0201_10V6K  [C_0201]  263.24 47.39 90 top
CE15  0.1U_0201_10V6K  [C_0201]  265.34 49.46 270 top
CE18  2200P_0402_50V7K  [C_0402]  260.46 50.76 180 top
CE19  2200P_0402_50V7K  [C_0402]  258.99 49.29 270 top
CE20  0.1U_0201_10V6K  [C_0201]  274.36 55.2 0 top
CE21  10P_0201_50V8J  [C_0201]  260.41 58.24 180 top
CE22  2200P_0402_50V7K  [C_0402]  268.87 63.39 180 top
CE23  2200P_0402_50V7K  [C_0402]  270.93 63.44 90 top
CE25  1U_0201_6.3V6M  [C_0201]  260.43 54.06 180 top
CE26  1U_0201_6.3V6M  [C_0201]  274.36 56.53 0 top
CE30  33P_0201_50V8J  [C_0201]  256.77 59.33 0 top
CE31  12P_0201_50V8J  [C_0201]  261.63 63.39 180 top
CE32  12P_0201_50V8J  [C_0201]  262.9 63.39 180 top
CE34  0.1U_0201_10V6K  [C_0201]  267.84 65.17 0 top
CE35  2.2U_0201_6.3V6M  [C_0201]  266.04 64.69 90 top
CE37  0.047U_0201_6.3V6K  [C_0201]  271.12 49.46 270 top
CE41  0.1U_0201_10V6K  [C_0201]  109.05 66.36 270 top
CE44  4700P_0402_25V7K  [C_0402]  274.48 53.87 0 top
CE50  0.1U_0201_10V6K  [C_0201]  267.22 64.53 180 top
CE55  100P_0201_50V8J  [C_0201]  255.33 60.92 0 top
CE57  100P_0201_50V8J  [C_0201]  80.15 42.94 180 top
CE58  100P_0201_50V8J  [C_0201]  95.08 15.37 0 top
CE60  100P_0201_50V8J  [C_0201]  36.9 14.14 180 top
CE69  100P_0201_50V8J  [C_0201]  193.71 55.68 270 bottom
CE112  2200P_0402_50V7K  [C_0402]  269.73 64.28 180 top
CE113  0.1U_0201_10V6K  [C_0201]  272.36 63.35 90 top
CE115  0.047U_0201_6.3V6K  [C_0201]  274.38 59.58 0 top
CE116  4700P_0402_25V7K  [C_0402]  257.47 60.03 90 top
CI9  0.1U_0201_10V6K  [C_0201]  283.15 47.64 0 top
CI10  0.1U_0201_10V6K  [C_0201]  283.15 47.07 0 top
CI11  0.1U_0201_10V6K  [C_0201]  283.73 46.18 180 top
CI12  0.1U_0201_10V6K  [C_0201]  283.73 45.61 180 top
CI13  0.1U_0201_10V6K  [C_0201]  285.72 42.73 270 top
CI14  0.01U_0201_10V6K  [C_0201]  288.9 49.89 90 top
CI21  47U_0603_6.3V6M  [C_0603]  294.49 47.14 270 bottom
CI22  47U_0603_6.3V6M  [C_0603]  293.22 47.14 270 bottom
CI23  0.1U_0201_10V6K  [C_0201]  292.91 47.9 180 bottom
CI24  22U_0603_10V6M  [C_0603]  284.52 63.52 180 top
CI25  1U_0402_25V6K  [C_0402]  284.45 62.4 180 top
CI26  0.1U_0201_10V6K  [C_0201]  18.12 12.46 180 bottom
CI27  0.1U_0201_10V6K  [C_0201]  18.12 11.89 180 bottom
CI28  47U_0603_6.3V6M  [C_0603]  16.56 14.43 90 bottom
CI29  47U_0603_6.3V6M  [C_0603]  15.34 14.43 90 bottom
CI30  0.1U_0201_10V6K  [C_0201]  15.23 13.61 0 bottom
CI31  22U_0603_10V6M  [C_0603]  20.93 16.21 90 top
CI32  1U_0402_25V6K  [C_0402]  19.63 16.21 90 top
CI35  0.1U_0201_10V6K  [C_0201]  294.96 53.93 0 top
CI36  0.1U_0201_10V6K  [C_0201]  294.96 53.36 0 top
CK1  1U_0201_10V6M  [C_0201]  211.05 17.43 90 top
CK2  10U_0402_10V6M  [C_0402]  212.95 18.38 270 top
CK3  1U_0201_10V6M  [C_0201]  214.1 18.47 270 top
CK8  0.1U_0201_10V6K  [C_0201]  234.92 20.08 180 top
CK9  0.1U_0201_10V6K  [C_0201]  228.75 11.75 180 top
CK10  0.1U_0201_10V6K  [C_0201]  239.24 11.19 270 top
CK11  0.1U_0201_10V6K  [C_0201]  242.54 13.57 90 top
CK12  4.7U_0402_6.3V6M  [C_0402]  226.62 13.85 180 top
CK13  0.1U_0201_10V6K  [C_0201]  242.54 17.51 90 top
CLCMOS1  SHORT PADS  [SHORTPADS]  96.62 26.69 270 bottom
CLEC1  SHORT PADS  [SHORTPADS]  275.94 56.41 90 top
CLIP1  -  [EMIST_SUL-12A2M_1P]  207.88 67.73 180 bottom
CLIP2  -  [EMIST_SUL-12A2M_1P]  202.88 55.34 270 bottom
CLIP3  -  [EMIST_SUL-12A2M_1P]  207.88 43.18 180 bottom
CLIP4  -  [EMIST_SUL-12A2M_1P]  266.88 21.9 180 bottom
CLIP5  -  [EMIST_SUL-12A2M_1P]  250.61 39.74 270 bottom
CLIP6  -  [EMIST_SUL-12A2M_1P]  283.26 39.74 270 bottom
CLME1  SHORT PADS  [SHORTPADS]  96.4 28.86 90 top
CM6  0.1U_0201_6.3V6K  [C_0201]  18.38 26.42 180 top
CM7  0.1U_0201_6.3V6K  [C_0201]  18.38 26.99 180 top
CM14  0.1U_0201_6.3V6K  [C_0201]  18.39 28.96 180 top
CM15  0.1U_0201_6.3V6K  [C_0201]  18.39 29.53 180 top
CM16  0.1U_0201_6.3V6K  [C_0201]  18.36 36.11 180 top
CM17  0.1U_0201_6.3V6K  [C_0201]  18.36 36.68 180 top
CM18  0.1U_0201_6.3V6K  [C_0201]  18.36 31.98 180 top
CM20  0.1U_0201_6.3V6K  [C_0201]  18.36 32.56 180 top
CM46  0.1U_0201_10V6K  [C_0201]  15.72 34.47 270 top
CM47  10U_0402_6.3V6M  [C_0402]  14.96 34.64 270 top
CM48  0.1U_0201_10V6K  [C_0201]  20.93 32.57 270 top
CM49  1P_0201_50V8C  [C_0201]  18.95 32.56 270 top
CM50  1P_0201_50V8C  [C_0201]  18.95 36.7 270 top
CM51  1P_0201_50V8C  [C_0201]  18.97 29.53 270 top
CM52  1P_0201_50V8C  [C_0201]  18.96 26.99 270 top
CN1  22U_0603_6.3V6M  [C_0603]  275.56 33.42 0 top
CN2  0.1U_0201_10V6K  [C_0201]  257.66 31.43 270 top
CN3  33P_0201_50V8J  [C_0201]  258.23 31.43 270 top
CN4  47P_0201_25V8J  [C_0201]  257.09 31.43 270 top
CN5  22U_0603_6.3V6M  [C_0603]  257.97 33.36 90 top
CN6  0.1U_0201_10V6K  [C_0201]  275.44 31.87 270 top
CN7  33P_0201_50V8J  [C_0201]  274.87 31.87 270 top
CN8  47P_0201_25V8J  [C_0201]  276.01 31.87 270 top
CN9  100U_A1_6.3VM_R70M  [C_NEC]  256.34 33.78 180 top
CN10  100U_A1_6.3VM_R70M  [C_NEC]  273.87 33.93 180 top
CN11  0.1U_0201_10V6K  [C_0201]  253.81 25.86 0 top
CN12  10U_0402_6.3V6M  [C_0402]  250.75 29.74 180 top
CN13  10U_0402_6.3V6M  [C_0402]  250.75 21.86 180 top
CN14  0.1U_0201_10V6K  [C_0201]  246.12 24.01 0 top
CN15  0.1U_0201_10V6K  [C_0201]  246.12 24.58 0 top
CN16  0.22U_0201_6.3V6M  [C_0201]  246.12 26.56 0 top
CN17  0.22U_0201_6.3V6M  [C_0201]  246.12 25.99 0 top
CN18  0.1U_0201_10V6K  [C_0201]  258.93 33.19 90 top
CN19  0.22U_0201_10V6K  [C_0201]  269.09 28.7 270 top
CN20  0.22U_0201_10V6K  [C_0201]  269.72 28.7 270 top
CN21  10P_0201_50V8J  [C_0201]  274.29 31.29 90 top
CN22  22U_0603_6.3V6M  [C_0603]  220.95 61.93 270 top
CN23  1U_0201_6.3V6M  [C_0201]  213.12 60.34 180 top
CN24  0.01U_0201_10V6K  [C_0201]  213.12 60.98 180 top
CN25  47P_0201_25V8J  [C_0201]  213.12 64.15 180 top
CN26  15P_0201_50V8J  [C_0201]  213.12 46.18 180 top
CN27  10U_0402_6.3V6M  [C_0402]  215.95 36.98 180 top
CN28  10U_0402_6.3V6M  [C_0402]  215.95 37.86 180 top
CN29  0.01U_0201_10V6K  [C_0201]  215.78 38.63 180 top
CN30  0.1U_0201_10V6K  [C_0201]  215.78 39.26 180 top
CN31  15P_0201_50V8J  [C_0201]  215.78 39.9 180 top
CN32  10U_0402_6.3V6M  [C_0402]  215.95 25.42 180 top
CN33  10U_0402_6.3V6M  [C_0402]  215.95 24.53 180 top
CN34  0.01U_0201_10V6K  [C_0201]  215.78 22.5 180 top
CN35  0.1U_0201_10V6K  [C_0201]  215.78 23.77 180 top
CN36  15P_0201_50V8J  [C_0201]  215.78 23.13 180 top
CN39  0.1U_0201_10V6K  [C_0201]  207.07 31.83 0 bottom
CN40  0.1U_0201_10V6K  [C_0201]  207.07 31.26 0 bottom
CN41  0.1U_0201_10V6K  [C_0201]  195.62 69.11 90 top
CN42  15P_0201_50V8J  [C_0201]  200.38 70.62 270 bottom
CN43  6.8NH_LQP03TN6N8J02D_5%  [MURAT_LQP03TN6N8J02D_2P]  201.01 70.62 270 bottom
CN44  4.7P_0201_50V8B  [C_0201]  199.74 70.62 270 bottom
CN45  1.2NH_LQP03TN1N2B02D_0.1NH  [MURAT_LQP03TN1N2B02D_2P]  199.11 70.62 270 bottom
CN46  1U_0201_6.3V6M  [C_0201]  213.12 46.75 180 top
CN47  22U_0603_6.3V6M  [C_0603]  212.83 45.42 270 top
CN48  0.01U_0201_10V6K  [C_0201]  213.12 47.33 180 top
CN49  0.22U_0201_10V6K  [C_0201]  205.56 62.19 180 top
CN50  0.22U_0201_10V6K  [C_0201]  205.56 61.61 180 top
CN51  0.22U_0201_10V6K  [C_0201]  205.56 59.2 180 top
CN52  0.22U_0201_10V6K  [C_0201]  205.56 58.63 180 top
CN53  0.22U_0201_10V6K  [C_0201]  205.56 56.15 180 top
CN54  0.22U_0201_10V6K  [C_0201]  205.56 55.58 180 top
CN55  0.22U_0201_10V6K  [C_0201]  205.56 53.17 180 top
CN56  0.22U_0201_10V6K  [C_0201]  205.56 52.6 180 top
CN57  0.1U_0201_10V6K  [C_0201]  260.26 42.35 270 top
CN58  0.1U_0201_10V6K  [C_0201]  260.26 36.89 270 top
CN59  47P_0201_25V8J  [C_0201]  273.4 24.48 270 top
CN60  15P_0201_50V8J  [C_0201]  197.37 73.87 90 top
CP1  15P_0201_50V8J  [C_0201]  191.26 19.51 90 bottom
CP2  1U_0201_6.3V6M  [C_0201]  190.63 19.51 90 bottom
CR1  0.1U_0201_10V6K  [C_0201]  292.33 32.02 270 top
CR2  10U_0402_10V6M  [C_0402]  291.57 31.9 270 top
CR3  4.7U_0402_6.3V6M  [C_0402]  293.93 40.39 90 top
CR4  0.1U_0201_10V6K  [C_0201]  293.61 39.59 0 top
CR5  1U_0201_6.3V6M  [C_0201]  296.99 33.93 0 top
CR6  0.1U_0201_10V6K  [C_0201]  289.1 34.19 0 top
CR8  2.2P_0201_25V8C  [C_0201]  297.57 32.66 180 top
CR9  10U_0402_10V6M  [C_0402]  298.55 33.47 90 top
CR10  0.1U_0201_10V6K  [C_0201]  299.31 33.64 90 top
CR11  4.7U_0402_6.3V6M  [C_0402]  298.55 37.41 90 top
CR12  0.1U_0201_10V6K  [C_0201]  299.31 37.66 90 top
CR13  1U_0201_6.3V6M  [C_0201]  296.99 36.87 0 top
CR14  4.7U_0402_6.3V6M  [C_0402]  293.09 31.9 270 top
CR15  0.1U_0201_10V6K  [C_0201]  291.44 34.05 180 bottom
CR16  0.1U_0201_10V6K  [C_0201]  293.85 32.02 270 top
CR17  0.1U_0201_10V6K  [C_0201]  289.1 33.62 0 top
CR18  1U_0201_6.3V6M  [C_0201]  285.57 40.29 90 top
CR20  0.1U_0201_10V6K  [C_0201]  284.26 40.07 0 top
CR21  0.1U_0201_10V6K  [C_0201]  289.1 36.73 0 top
CR22  0.1U_0201_10V6K  [C_0201]  289.1 36.16 0 top
CS1  47P_0201_25V8J  [C_0201]  290.99 31.04 270 bottom
CS2  2.2P_0201_25V8C  [C_0201]  291.6 33.42 180 bottom
CS3  2.2P_0201_25V8C  [C_0201]  291.57 32.82 270 bottom
CS4  2.2P_0201_25V8C  [C_0201]  291.6 31.64 180 bottom
CS5  33P_0201_50V8J  [C_0201]  290.99 32.82 270 bottom
CS6  2.2P_0201_25V8C  [C_0201]  291.57 31.04 270 bottom
CS7  0.1U_0201_10V6K  [C_0201]  292.96 38.46 90 bottom
CS8  4.7U_0402_6.3V6M  [C_0402]  293.72 38.3 90 bottom
CS9  0.1U_0201_10V6K  [C_0201]  197.94 63.52 180 bottom
CS10  100P_0201_50V8J  [C_0201]  199.34 66.4 90 bottom
CS11  100P_0201_50V8J  [C_0201]  196.19 69.11 90 top
CS12  27P_0201_25V8  [C_0201]  206.6 70.95 270 bottom
CS13  27P_0201_25V8  [C_0201]  209.02 70.92 270 bottom
CS14  27P_0201_25V8  [C_0201]  202.83 68.27 90 top
CS15  27P_0201_25V8  [C_0201]  197.24 68.46 0 top
CT1  0.22U_0201_6.3V6M  [C_0201]  27.66 46.03 270 bottom
CT2  0.22U_0201_6.3V6M  [C_0201]  27.1 45.45 90 bottom
CT3  0.22U_0201_6.3V6M  [C_0201]  28.22 46.03 270 bottom
CT4  0.22U_0201_6.3V6M  [C_0201]  26.54 45.45 90 bottom
CT5  0.22U_0201_6.3V6M  [C_0201]  25.42 46.03 270 bottom
CT6  0.22U_0201_6.3V6M  [C_0201]  22.63 45.45 90 bottom
CT7  0.22U_0201_6.3V6M  [C_0201]  23.74 46.03 270 bottom
CT8  0.22U_0201_6.3V6M  [C_0201]  22.07 45.45 90 bottom
CT9  0.22U_0201_6.3V6M  [C_0201]  21.51 46.03 270 bottom
CT10  0.22U_0201_6.3V6M  [C_0201]  20.39 45.45 90 bottom
CT11  0.22U_0201_6.3V6M  [C_0201]  20.95 46.03 270 bottom
CT12  0.22U_0201_6.3V6M  [C_0201]  19.83 45.45 90 bottom
CT13  0.1U_0201_6.3V6K  [C_0201]  29.83 54.83 0 bottom
CT14  0.1U_0201_6.3V6K  [C_0201]  29.83 54.27 0 bottom
CT15  0.1U_0201_6.3V6K  [C_0201]  31.5 53.54 0 bottom
CT16  0.1U_0201_6.3V6K  [C_0201]  29.83 52.79 0 bottom
CT17  0.1U_0201_6.3V6K  [C_0201]  31.5 52.98 0 bottom
CT18  0.1U_0201_6.3V6K  [C_0201]  31.5 52.42 0 bottom
CT19  0.22U_0201_6.3V6M  [C_0201]  24.86 45.45 90 bottom
CT20  0.22U_0201_6.3V6M  [C_0201]  25.98 46.03 270 bottom
CT21  0.22U_0201_6.3V6M  [C_0201]  24.3 45.45 90 bottom
CT22  0.22U_0201_6.3V6M  [C_0201]  23.19 46.03 270 bottom
CT23  0.1U_0201_6.3V6K  [C_0201]  31.5 54.1 0 bottom
CT24  0.1U_0201_6.3V6K  [C_0201]  29.83 53.35 0 bottom
CT25  0.1U_0201_6.3V6K  [C_0201]  31.49 51.3 0 bottom
CT26  0.1U_0201_6.3V6K  [C_0201]  31.49 51.86 0 bottom
CT27  0.1U_0201_6.3V6K  [C_0201]  29.83 51.66 0 bottom
CT28  0.1U_0201_6.3V6K  [C_0201]  29.83 51.1 0 bottom
CT29  0.1U_0201_6.3V6K  [C_0201]  31.5 49.07 0 bottom
CT30  0.1U_0201_6.3V6K  [C_0201]  31.5 49.63 0 bottom
CT31  0.1U_0201_6.3V6K  [C_0201]  29.83 48.33 0 bottom
CT32  0.1U_0201_6.3V6K  [C_0201]  29.83 48.89 0 bottom
CT33  0.1U_0201_6.3V6K  [C_0201]  29.83 46.96 0 bottom
CT34  0.1U_0201_6.3V6K  [C_0201]  29.83 47.52 0 bottom
CT35  0.1U_0201_6.3V6K  [C_0201]  31.5 50.75 0 bottom
CT36  0.1U_0201_6.3V6K  [C_0201]  31.5 50.19 0 bottom
CT37  27P_0201_25V8  [C_0201]  18.84 44.76 0 bottom
CT38  27P_0201_25V8  [C_0201]  18.26 44.76 180 bottom
CT39  0.22U_0201_6.3V6M  [C_0201]  17.34 50.5 180 bottom
CT40  0.22U_0201_6.3V6M  [C_0201]  17.34 54.71 180 bottom
CT41  0.22U_0201_6.3V6M  [C_0201]  17.34 49.94 180 bottom
CT42  0.22U_0201_6.3V6M  [C_0201]  17.34 54.15 180 bottom
CT43  0.22U_0201_6.3V6M  [C_0201]  17.34 48.37 180 bottom
CT44  0.22U_0201_6.3V6M  [C_0201]  17.34 52.04 180 bottom
CT45  0.22U_0201_6.3V6M  [C_0201]  17.34 48.92 180 bottom
CT46  0.22U_0201_6.3V6M  [C_0201]  17.34 52.6 180 bottom
CT47  0.1U_0201_6.3V6K  [C_0201]  29.83 50.37 0 bottom
CT48  0.1U_0201_6.3V6K  [C_0201]  31.5 48.33 0 bottom
CT49  0.1U_0201_6.3V6K  [C_0201]  29.83 49.81 0 bottom
CT50  0.1U_0201_6.3V6K  [C_0201]  31.5 47.77 0 bottom
CT51  0.1U_0201_10V6K  [C_0201]  30.62 50.56 180 top
CT52  1U_0201_6.3V6M  [C_0201]  23.58 54.87 90 top
CT53  1U_0201_6.3V6M  [C_0201]  23.58 54.22 0 top
CT54  1U_0201_6.3V6M  [C_0201]  26.18 51.7 270 top
CT55  1U_0201_6.3V6M  [C_0201]  22.93 52.27 270 top
CT56  1U_0201_6.3V6M  [C_0201]  22.93 52.92 180 top
CT57  1U_0201_6.3V6M  [C_0201]  22.93 54.87 90 top
CT58  1U_0201_6.3V6M  [C_0201]  26.18 52.27 0 top
CT59  0.1U_0201_10V6K  [C_0201]  24.88 55.99 0 top
CT60  1U_0201_6.3V6M  [C_0201]  21 54.25 90 top
CT61  1U_0201_6.3V6M  [C_0201]  18.55 56.19 0 top
CT62  10U_0402_6.3V6M  [C_0402]  17.18 55.07 270 top
CT63  10U_0402_6.3V6M  [C_0402]  20.05 61.9 180 top
CT64  10U_0402_6.3V6M  [C_0402]  20.05 61.02 180 top
CT65  10U_0402_6.3V6M  [C_0402]  20.05 60.13 180 top
CT66  1U_0201_6.3V6M  [C_0201]  24.88 50.5 0 top
CT67  1U_0201_6.3V6M  [C_0201]  24.23 49.11 180 top
CT68  1U_0201_6.3V6M  [C_0201]  24.23 48.56 180 top
CT69  1U_0201_6.3V6M  [C_0201]  23.61 50.28 270 top
CT70  1U_0201_6.3V6M  [C_0201]  22.93 48.5 180 top
CT71  1U_0201_6.3V6M  [C_0201]  24.88 49.85 0 top
CT72  1U_0201_6.3V6M  [C_0201]  23.58 53.57 270 top
CT73  1U_0201_6.3V6M  [C_0201]  22.93 53.57 90 top
CT74  1U_0201_6.3V6M  [C_0201]  22.28 53.57 90 top
CT75  1U_0201_6.3V6M  [C_0201]  19.83 50.39 90 top
CT76  1U_0201_6.3V6M  [C_0201]  20.33 51.62 180 top
CT77  1U_0201_6.3V6M  [C_0201]  20.33 52.27 180 top
CT78  1U_0201_6.3V6M  [C_0201]  20.99 52.93 180 top
CT79  47U_0603_6.3V  [C_0603]  16.84 61.75 0 top
CT80  47U_0603_6.3V  [C_0603]  16.84 60.56 0 top
CT81  47U_0603_6.3V  [C_0603]  16.84 59.36 0 top
CT94  2.2U_0201_6.3V6M  [C_0201]  29.21 65.19 0 top
CT95  2.2U_0201_6.3V6M  [C_0201]  27.98 70.15 90 top
CT96  2.2U_0201_6.3V6M  [C_0201]  29.15 68.22 0 top
CT97  2.2U_0201_6.3V6M  [C_0201]  29.21 72.47 0 top
CT98  2.2U_0201_6.3V6M  [C_0201]  27.98 77.32 90 top
CT99  2.2U_0201_6.3V6M  [C_0201]  29.15 75.39 0 top
CT100  10U_0603_25V6M  [C_0603]  8.61 55.87 90 bottom
CT101  0.1U_0402_25V6  [C_0402]  4.36 54.95 180 bottom
CT102  0.1U_0402_25V6  [C_0402]  4.36 70.17 180 bottom
CT103  10U_0603_25V6M  [C_0603]  9.5 73.01 90 top
CT104  0.47U_0201_25V6M  [C_0201]  5.49 67.16 90 bottom
CT105  0.47U_0201_25V6M  [C_0201]  5.49 71.86 270 bottom
CT106  0.47U_0201_25V6M  [C_0201]  5.49 56.64 270 bottom
CT107  0.47U_0201_25V6M  [C_0201]  5.49 51.94 90 bottom
CT108  0.47U_0201_25V6M  [C_0201]  9.6 74.82 180 bottom
CT109  0.47U_0201_25V6M  [C_0201]  3.44 69.28 0 bottom
CT110  0.47U_0201_25V6M  [C_0201]  3.44 55.84 0 bottom
CT111  0.47U_0201_25V6M  [C_0201]  3.44 54.06 0 bottom
CT129  1U_0201_6.3V6M  [C_0201]  22.93 50.94 180 top
CT130  1U_0201_6.3V6M  [C_0201]  21.77 50.32 180 top
CT131  1U_0201_6.3V6M  [C_0201]  24.9 51.06 0 top
CT132  47U_0603_6.3V  [C_0603]  18.86 50.88 180 top
CT133  47U_0603_6.3V  [C_0603]  18.86 52.07 180 top
CT134  1U_0201_6.3V6M  [C_0201]  24.88 52.27 0 top
CT135  1U_0201_6.3V6M  [C_0201]  24.88 54.22 0 top
CT136  1U_0201_6.3V6M  [C_0201]  24.88 53.57 180 top
CT137  1U_0201_6.3V6M  [C_0201]  20.52 49.67 270 top
CT138  1U_0201_6.3V6M  [C_0201]  21.17 49.67 270 top
CT139  10U_0402_6.3V6M  [C_0402]  18.9 49.56 270 top
CT140  10U_0402_6.3V6M  [C_0402]  19.79 49.56 270 top
CT141  100P_0201_50V8J  [C_0201]  27.11 59.39 90 bottom
CT142  0.1U_0201_10V6K  [C_0201]  31.49 63.32 0 top
CT143  39P_0201_50V8J  [C_0201]  24.9 51.62 0 top
CT144  100P_0201_50V8J  [C_0201]  24.27 51.63 90 top
CT145  39P_0201_50V8J  [C_0201]  20.27 54.87 180 top
CT146  100P_0201_50V8J  [C_0201]  20.27 54.22 180 top
CT147  39P_0201_50V8J  [C_0201]  24.88 56.55 0 top
CT148  100P_0201_50V8J  [C_0201]  24.88 55.43 0 top
CT149  39P_0201_50V8J  [C_0201]  18.5 57.34 90 top
CT150  100P_0201_50V8J  [C_0201]  21.65 53.61 90 top
CT151  39P_0201_50V8J  [C_0201]  26.18 52.92 90 top
CT152  100P_0201_50V8J  [C_0201]  25.57 52.91 90 top
CT153  39P_0201_50V8J  [C_0201]  23.6 51.69 90 top
CT154  100P_0201_50V8J  [C_0201]  23.64 50.96 0 top
CT155  39P_0201_50V8J  [C_0201]  20.98 50.97 180 top
CT156  100P_0201_50V8J  [C_0201]  21.01 52.19 270 top
CT157  39P_0201_50V8J  [C_0201]  24.88 48.65 0 top
CT158  100P_0201_50V8J  [C_0201]  24.88 49.2 0 top
CT159  39P_0201_50V8J  [C_0201]  21.63 52.92 270 top
CT160  100P_0201_50V8J  [C_0201]  22.26 52.35 270 top
CT161  39P_0201_50V8J  [C_0201]  24.88 54.87 0 top
CT162  100P_0201_50V8J  [C_0201]  24.88 52.92 180 top
CT163  39P_0201_50V8J  [C_0201]  22.93 50.32 180 top
CT164  100P_0201_50V8J  [C_0201]  22.93 49.65 180 top
CT165  39P_0201_50V8J  [C_0201]  21.64 51.03 90 top
CT166  100P_0201_50V8J  [C_0201]  21.73 49.67 270 top
CT167  39P_0201_50V8J  [C_0201]  19.27 58.35 0 top
CT168  100P_0201_50V8J  [C_0201]  19.26 58.93 0 top
CT169  39P_0201_50V8J  [C_0201]  19.66 57.78 180 top
CT170  100P_0201_50V8J  [C_0201]  20.24 57.78 0 top
CT171  10U_0402_6.3V6M  [C_0402]  29.23 68.98 0 top
CT172  1U_0402_25V6K  [C_0402]  19.28 67.07 90 bottom
CT173  1U_0201_6.3V6M  [C_0201]  27.51 66.25 180 top
CT174  10U_0402_6.3V6M  [C_0402]  29.37 66.59 90 top
CT175  22U_0603_6.3V6M  [C_0603]  19.23 69.44 90 bottom
CT176  22U_0603_6.3V6M  [C_0603]  20.43 69.44 90 bottom
CT177  22U_0603_6.3V6M  [C_0603]  21.62 69.44 90 bottom
CT178  22U_0603_6.3V6M  [C_0603]  21.75 68.37 180 bottom
CT179  1U_0402_25V6K  [C_0402]  21.79 66.44 90 bottom
CT180  220P_0201_25V7K  [C_0201]  23.72 65.89 90 top
CT181  220P_0201_25V7K  [C_0201]  24.29 65.89 90 top
CT182  0.22U_0201_6.3V6M  [C_0201]  24.87 65.89 90 top
CT183  10U_0402_6.3V6M  [C_0402]  29.23 76.16 0 top
CT184  1U_0402_25V6K  [C_0402]  19.07 73.97 90 bottom
CT185  1U_0201_6.3V6M  [C_0201]  27.52 73.42 180 top
CT186  10U_0402_6.3V6M  [C_0402]  29.37 73.77 90 top
CT187  22U_0603_6.3V6M  [C_0603]  21.54 76.37 90 bottom
CT188  22U_0603_6.3V6M  [C_0603]  21.68 75.3 180 bottom
CT189  22U_0603_6.3V6M  [C_0603]  20.35 76.37 90 bottom
CT190  22U_0603_6.3V6M  [C_0603]  19.16 76.37 90 bottom
CT191  1U_0402_25V6K  [C_0402]  21.7 73.36 90 bottom
CT192  220P_0201_25V7K  [C_0201]  23.72 73.13 90 top
CT193  220P_0201_25V7K  [C_0201]  24.29 73.13 90 top
CT194  0.22U_0201_6.3V6M  [C_0201]  24.87 73.13 90 top
CT195  100P_0201_50V8J  [C_0201]  29.21 65.77 0 top
CT196  100P_0201_50V8J  [C_0201]  22.83 70.15 90 top
CT197  100P_0201_50V8J  [C_0201]  23.47 70.15 90 top
CT198  100P_0201_50V8J  [C_0201]  29.21 73.04 0 top
CT199  100P_0201_50V8J  [C_0201]  23.09 77.32 90 top
CT200  100P_0201_50V8J  [C_0201]  23.72 77.32 90 top
CT201  1U_0603_25V6K  [C_0603]  14.52 67.63 90 bottom
CT202  1U_0402_10V6K  [C_0402]  12.78 71.01 180 bottom
CT204  0.01U_0201_10V6K  [C_0201]  14.48 70.94 0 bottom
CT205  0.1U_0201_25V6K  [C_0201]  16.84 74.31 180 bottom
CT206  1U_0402_25V6K  [C_0402]  10.07 70.07 270 bottom
CV1  0.1U_0201_10V6K  [C_0201]  43.71 71.77 0 top
CV2  10U_0402_6.3V6M  [C_0402]  43.8 72.54 0 top
CV3  10U_0402_6.3V6M  [C_0402]  37.39 73.62 180 top
CV4  0.1U_0201_10V6K  [C_0201]  38.07 75.33 0 top
CV5  0.1U_0201_10V6K  [C_0201]  44.72 73.48 90 top
CV6  0.1U_0201_10V6K  [C_0201]  44.14 73.48 90 top
CV7  0.1U_0201_10V6K  [C_0201]  46.01 73.51 90 top
CV8  0.1U_0201_10V6K  [C_0201]  45.44 73.51 90 top
CV13  0.1U_0402_25V6  [C_0402]  31.09 74.82 90 top
CV16  0.1U_0402_25V6  [C_0402]  35.18 71.09 270 top
